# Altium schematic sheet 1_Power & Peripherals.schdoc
size 309 x 223 mm; Symbol: Artery_A4; Device: Artery_A4; Company: Artery Technology; Drawed: SD; Version: 1.0; Page Size: A4; @Project Name: AT-START-F405; @Page Count: 4; @Update Date: 2023-08-24; @Create Date: 2023-05-06; @Schematic Name: AT-START-F405; @Page No: 3; @Page Name: Power & Peripherals
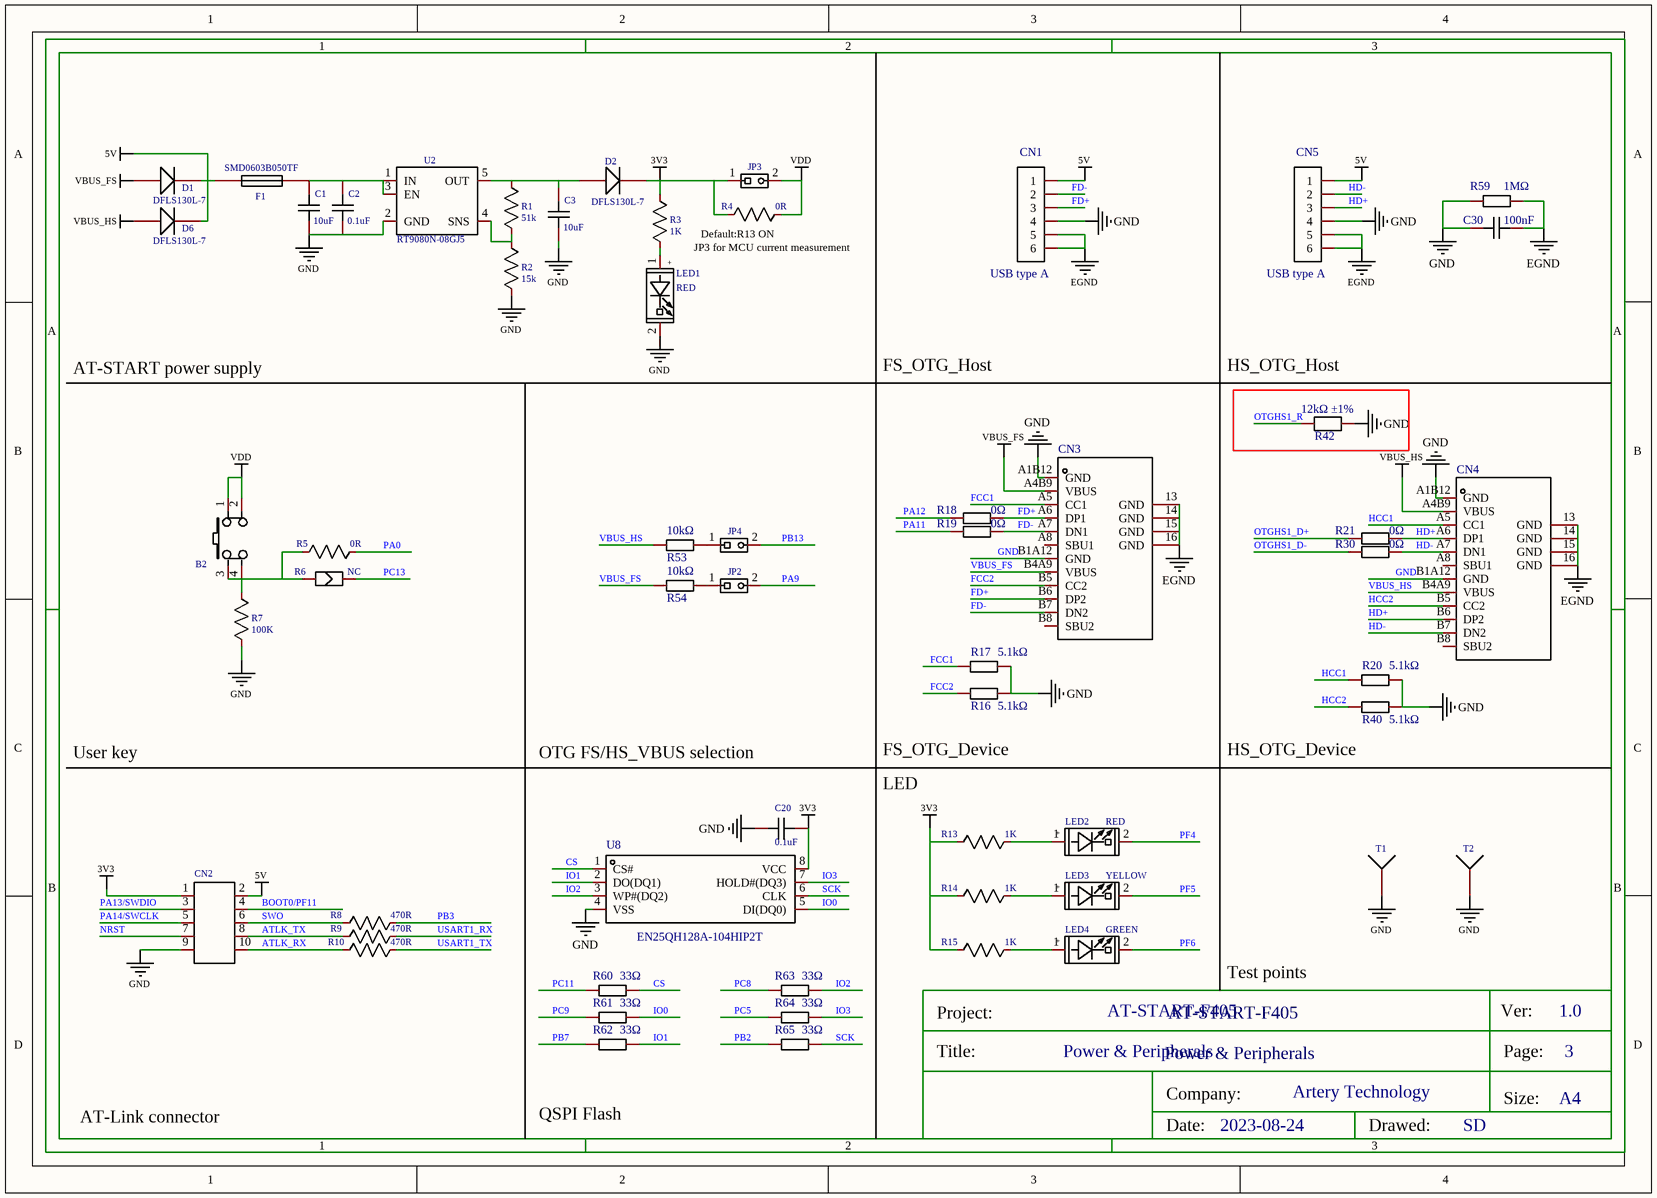
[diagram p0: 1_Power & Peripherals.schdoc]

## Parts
B2  BUTTON_SMT,6.0x6.0x4.5mm  [BUTTON_SMT_6*6*5]  (value not drawn)
C1  10uF  [0603_C-M]
C2  0.1uF  [0603_C-M]
C3  10uF  [0603_C-M]
C20  0.1uF  [0603_C-M]
C30  value 100nF  [C0603]  (hidden comment: CC0603KRX7R9BB104)
CN1  USB type A  [USB-A-TH__USB-AF-90]
CN2  NC(Header 2x5)  [HDR2X5]  (value not drawn)
CN3  TYPEC-304-BCP16  [USB-C-SMD_TYPEC-304-BCP16]  (value not drawn)
CN4  TYPEC-304-BCP16  [USB-C-SMD_TYPEC-304-BCP16]  (value not drawn)
CN5  USB type A  [USB-A-TH__USB-AF-90]
D1  DFLS130L-7  [SOD-123]
D2  DFLS130L-7  [SOD-123]
D6  DFLS130L-7  [SOD-123]
F1  SMD0603B050TF  [R0603]
JP2  NC(Header 1x2)  [HEADER 1X2]  (value not drawn)
JP3  NC(Header 1x2)  [HEADER 1X2]  (value not drawn)
JP4  NC(Header 1x2)  [HEADER 1X2]  (value not drawn)
LED1  RED  [LED0603]
LED2  RED  [LED0603]
LED3  YELLOW  [LED0603]
LED4  GREEN  [LED0603]
R1  51k  [0603_R-M]
R2  15k  [0603_R-M]
R3  1K  [0603_R-M]
R4  0R  [0603_R-M]
R5  0R  [0603_R-M]
R6  NC  [SB-PAD]
R7  100K  [0603_R-M]
R8  470R  [0603_R-M]
R9  470R  [0603_R-M]
R10  470R  [0603_R-M]
R13  1K  [0603_R-M]
R14  1K  [0603_R-M]
R15  1K  [0603_R-M]
R16  value 5.1kΩ  [R0603]  (hidden comment: 0603WAF5101T5E)
R17  value 5.1kΩ  [R0603]  (hidden comment: 0603WAF5101T5E)
R18  value 0Ω  [R0603]  (hidden comment: 0603WAF220JT5E)
R19  value 0Ω  [R0603]  (hidden comment: 0603WAF220JT5E)
R20  value 5.1kΩ  [R0603]  (hidden comment: 0603WAF5101T5E)
R21  value 0Ω  [R0603]  (hidden comment: 0603WAF220JT5E)
R30  value 0Ω  [R0603]  (hidden comment: 0603WAF220JT5E)
R40  value 5.1kΩ  [R0603]  (hidden comment: 0603WAF5101T5E)
R42  LCSC Part Name: 12kΩ ±1%  [R0603]  (hidden comment: 0603WAD1202T5E)
R53  value 10kΩ  [R0603]  (hidden comment: 0603WAF1002T5E)
R54  value 10kΩ  [R0603]  (hidden comment: 0603WAF1002T5E)
R59  value 1MΩ  [R0603]  (hidden comment: RC0603FR-071ML)
R60  value 33Ω  [R0603]  (hidden comment: 0603WAF330JT5E)
R61  value 33Ω  [R0603]  (hidden comment: 0603WAF330JT5E)
R62  value 33Ω  [R0603]  (hidden comment: 0603WAF330JT5E)
R63  value 33Ω  [R0603]  (hidden comment: 0603WAF330JT5E)
R64  value 33Ω  [R0603]  (hidden comment: 0603WAF330JT5E)
R65  value 33Ω  [R0603]  (hidden comment: 0603WAF330JT5E)
T1  Testpoint  [TESTHOOK]  (value not drawn)
T2  Testpoint  [TESTHOOK]  (value not drawn)
U2  RT9080N-08GJ5  [SOT-23-5]
U8  EN25QH128A-104HIP2T  [SOP-8_L5.3-W5.3-P1.27-LS8.0-BL]

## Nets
3V3: C20.2 CN2.1 D2.2(K) JP3.1 R3.1 R4.2 R13.2 R14.2 R15.2 U8.8(VCC)
5V: CN1.1 CN2.2 CN5.1 D1.2(K) D6.2(K) F1.1
EGND: C30.2 CN1.SH1(5) CN1.SH2(6) CN3.13(GND) CN3.14(GND) CN3.15(GND) CN3.16(GND) CN4.13(GND) CN4.14(GND) CN4.15(GND) CN4.16(GND) CN5.SH1(5) CN5.SH2(6) R59.1
GND: C1.2 C2.2 C3.2 C20.1 C30.1 CN1.4 CN2.9 CN3.A1B12(GND) CN3.B1A12(GND) CN4.A1B12(GND) CN4.B1A12(GND) CN5.4 LED1.2(CATHODE) R2.1 R7.2 R16.2 R17.2 R20.2 R40.2 R42.2 R59.2 T1.1 T2.1 U2.2(GND) U8.4(VSS)
VBUS_FS: CN3.A4B9(VBUS) CN3.B4A9(VBUS) D1.1(A) R54.2
VBUS_HS: CN4.A4B9(VBUS) CN4.B4A9(VBUS) D6.1(A) R53.2
VDD: B2.1 B2.2 JP3.2 R4.1
ATLK_RX: CN2.10 R10.2
ATLK_TX: CN2.8 R9.2
BOOT0/PF11: CN2.4
CS: R60.2 U8.1(CS#)
FCC1: CN3.A5(CC1) R17.1
FCC2: CN3.B5(CC2) R16.1
FD+: CN1.3 CN3.A6(DP1) CN3.B6(DP2) R18.2
FD-: CN1.2 CN3.A7(DN1) CN3.B7(DN2) R19.2
HCC1: CN4.A5(CC1) R20.1
HCC2: CN4.B5(CC2) R40.1
HD+: CN4.A6(DP1) CN4.B6(DP2) CN5.3 R21.2
HD-: CN4.A7(DN1) CN4.B7(DN2) CN5.2 R30.2
IO0: R61.2 U8.5(DI(DQ0))
IO1: R62.2 U8.2(DO(DQ1))
IO2: R63.2 U8.3(WP#(DQ2))
IO3: R64.2 U8.7(HOLD#(DQ3))
NRST: CN2.7
OTGHS1_D+: R21.1
OTGHS1_D-: R30.1
OTGHS1_R: R42.1
PA0: R5.1
PA9: JP2.2
PA11: R19.1
PA12: R18.1
PA13/SWDIO: CN2.3
PA14/SWCLK: CN2.5
PB2: R65.1
PB3: R8.1
PB7: R62.1
PB13: JP4.2
PC5: R64.1
PC8: R63.1
PC9: R61.1
PC11: R60.1
PC13: R6.2
PF4: LED2.2(CATHODE)
PF5: LED3.2(CATHODE)
PF6: LED4.2(CATHODE)
SCK: R65.2 U8.6(CLK)
SWO: CN2.6 R8.2
USART1_RX: R9.1
USART1_TX: R10.1
NetB2_3: B2.3 B2.4 R5.2 R6.1 R7.1
NetC1_1: C1.1 C2.1 F1.2 U2.1(IN) U2.3(EN)
NetC3_1: C3.1 D2.1(A) R1.2 U2.5(OUT)
NetJP2_1: JP2.1 R54.1
NetJP4_1: JP4.1 R53.1
NetLED1_1: LED1.1(ANODE) R3.2
NetLED2_1: LED2.1(ANODE) R13.1
NetLED3_1: LED3.1(ANODE) R14.1
NetLED4_1: LED4.1(ANODE) R15.1
NetR1_1: R1.1 R2.2 U2.4(SNS)

Not connected (* = marked no-connect by the designer): CN3 A8(SBU1) B8(SBU2); CN4 A8(SBU1) B8(SBU2)

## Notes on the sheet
- JP3 for MCU current measurement
- (near R4) Default:R13 ON
- AT-START power supply
- FS_OTG_Host
- (near R42) HS_OTG_Host
- User key
- OTG FS/HS_VBUS selection
- LED
- FS_OTG_Device
- (near R40) HS_OTG_Device
- Test points
- AT-START-F405
- Power & Peripherals
- AT-Link connector
- QSPI Flash

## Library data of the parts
B2 = BUTTON_SMT,6.0x6.0x4.5mm: Convert to PCB: yes
C1 C3 = 10uF: Convert to PCB: yes
C2 C20 = 0.1uF: Convert to PCB: yes
C30 = CC0603KRX7R9BB104: 容值:100nF;精度:±10%;额定电压:50V;温度系数:X7R;; Manufacturer: YAGEO(国巨); Add into BOM: yes; Tolerance: ±10%; Voltage Rated: 50V; Temperature Coefficient: X7R; NAME: 2; Pin Type: IN
CN1 CN5 = USB type A: Convert to PCB: yes
CN2 = NC(Header 2x5): Convert to PCB: yes
CN3 CN4 = TYPEC-304-BCP16: 连接器类型:Type-C;标准:USB 3.1;公母:母座;触点数量:16.0;端口数量:1;安装方式:卧贴;额定电流 - 电源:3A;工作温度范围:-25~+85;焊接温度(最大值):260;; Manufacturer: XUNPU(讯普); Add into BOM: yes; Connector Type: Type-C; Gender: 母座; Number of Contacts: 16.0; Number of Ports: 1; Mounting Sytle: 卧贴; Current Rating - Power (Max): 3A; Welding Temperature (Max): 260; Pin Type: IN
D1 D2 D6 = DFLS130L-7: Convert to PCB: yes
F1 = SMD0603B050TF: Convert to PCB: yes
JP2-JP4 = NC(Header 1x2): Convert to PCB: yes
LED1 LED2 = RED: Convert to PCB: yes
LED3 = YELLOW: Convert to PCB: yes
LED4 = GREEN: Convert to PCB: yes
R1 = 51k: Convert to PCB: yes
R2 = 15k: Convert to PCB: yes
R3 R13-R15 = 1K: Convert to PCB: yes
R4 R5 = 0R: Convert to PCB: yes
R6 = NC: Convert to PCB: yes
R7 = 100K: Convert to PCB: yes
R8-R10 = 470R: Convert to PCB: yes
R16 R17 R20 R40 = 0603WAF5101T5E: 电阻类型:厚膜电阻;阻值:5.1kΩ;精度:±1%;功率:1/10W;温度系数:±100ppm/;最大工作电压:75V;工作温度范围:-55~+155;; Manufacturer: UNI-ROYAL(厚声); Add into BOM: yes; Tolerance: ±1%; Power(Watts): 1/10W; Overload Voltage (Max): 75V; NAME: 1; Pin Type: IN
R18 R19 R21 R30 = 0603WAF220JT5E: 电阻类型:厚膜电阻;阻值:22Ω;精度:±1%;功率:100mW;温度系数:±100ppm/;最大工作电压:75V;工作温度范围:-55~+155;; Manufacturer: UNI-ROYAL(厚声); Add into BOM: yes; Tolerance: ±1%; Power(Watts): 100mW; Overload Voltage (Max): 75V; NAME: 1; Pin Type: IN
R42 = 0603WAD1202T5E: 电阻类型:厚膜电阻;阻值:12kΩ;精度:±0.5%;功率:1/10W;温度系数:±100ppm/℃;最大工作电压:75V;工作温度范围:-55℃~+155℃;; Manufacturer: UNI-ROYAL(厚声); Add into BOM: yes; Value: 12kΩ; Tolerance: ±0.5%; Power(Watts): 1/10W; Overload Voltage (Max): 75V; NAME: 1; Pin Type: IN
R53 R54 = 0603WAF1002T5E: 电阻类型:厚膜电阻;阻值:10kΩ;精度:±1%;功率:1/10W;温度系数:±100ppm/;最大工作电压:75V;工作温度范围:-55~+155;; Manufacturer: UNI-ROYAL(厚声); Add into BOM: yes; Tolerance: ±1%; Power(Watts): 1/10W; Overload Voltage (Max): 75V; NAME: 1; Pin Type: IN
R59 = RC0603FR-071ML: 阻值:1MΩ;精度:±1%;功率:100mW;温度系数:±100ppm/;最大工作电压:75V;工作温度范围:-55~+155;; Manufacturer: YAGEO(国巨); Add into BOM: yes; Tolerance: ±1%; Power(Watts): 100mW; Overload Voltage (Max): 75V; NAME: 1; Pin Type: IN
R60-R65 = 0603WAF330JT5E: 电阻类型:厚膜电阻;阻值:33Ω;精度:±1%;功率:100mW;; Manufacturer: UNI-ROYAL(厚声); Add into BOM: yes; Tolerance: ±1%; Power(Watts): 100mW; Temperature Coefficient: ±100ppm/℃; Overload Voltage (Max): 75V; NAME: 1; Pin Type: IN
T1 T2 = Testpoint: Convert to PCB: yes
U2 = RT9080N-08GJ5: Convert to PCB: yes
U8 = EN25QH128A-104HIP2T: 接口类型:SPI;存储容量:128Mbit;时钟频率(fc):104MHz;; Manufacturer: ESMT(晶豪); Add into BOM: yes; Interface Type: SPI; Clock Frequency (fc): 104MHz; Supply Voltage: 2.7V~3.6V; Supply Current (Read): 25mA; Supply Current (Program): 28mA; Standby supply current: 20uA; Page Programming Time (Tpp): 800us; Block Erase Time (tBE): 200ms@(64KB); Data Retention - TDR (Year): 20年; Pin Type: IN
